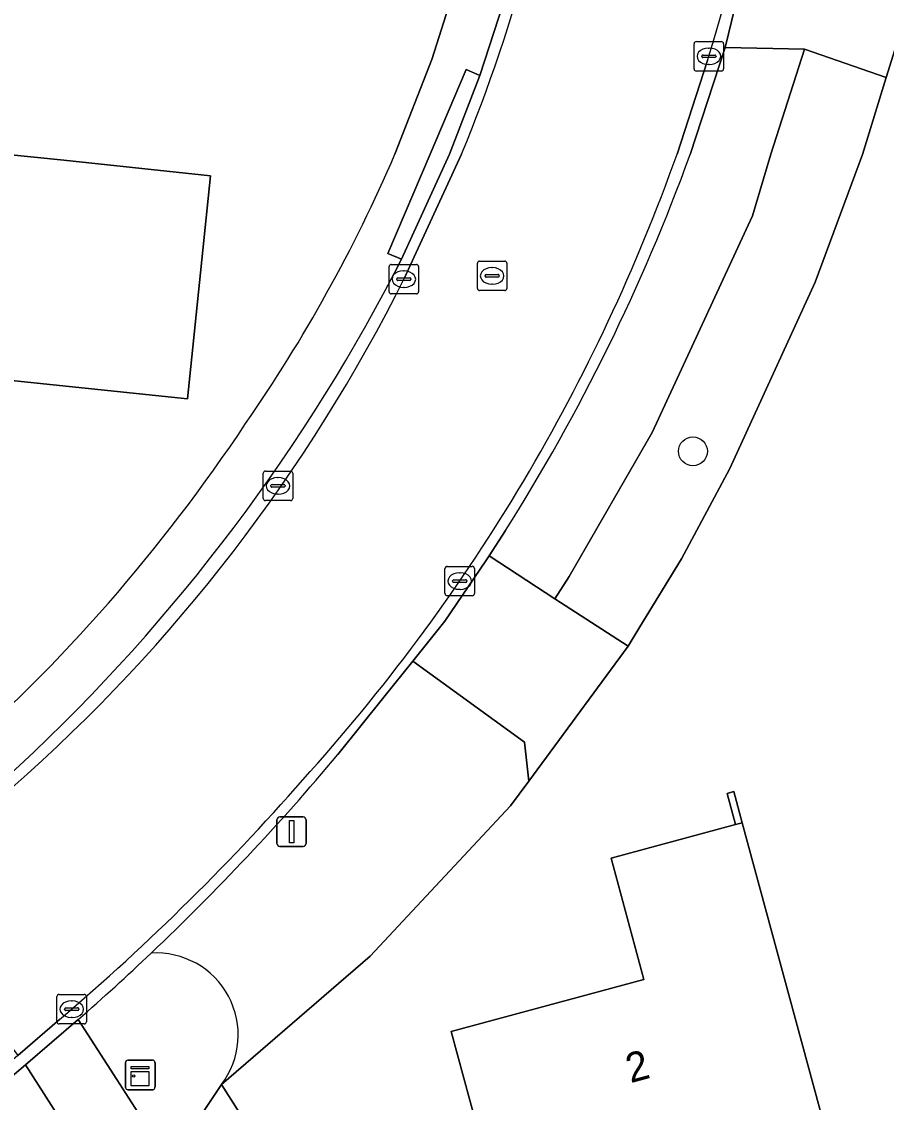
# Model space of a CAD drawing. Extents: x 162156 to 163172, y 378995 to 380779.
# Drawn here: x 162699.46 to 162728.79, y 380217.85 to 380254.49 of the extents above; entities that cross this region are included whole.
import ezdxf

# ---------------------------------------------------------------- set-up
doc = ezdxf.new("R2010")
doc.units = 0
for name, color, linetype in [('IMGEO_Berm_groen', 7, 'Continuous'), ('IMGEO_Boom', 7, 'Continuous'), ('IMGEO_Erf', 7, 'Continuous'), ('IMGEO_Gemengd_bos', 7, 'Continuous'), ('IMGEO_Groenvoorziening', 7, 'Continuous'), ('IMGEO_Kast', 7, 'Continuous'), ('IMGEO_Kolk', 7, 'Continuous'), ('IMGEO_Lichtmast', 7, 'Continuous'), ('IMGEO_Muur', 7, 'Continuous'), ('IMGEO_Naaldbos', 7, 'Continuous'), ('IMGEO_Pand', 7, 'Continuous'), ('IMGEO_Pand_nummerreeks', 7, 'Continuous'), ('IMGEO_Rijbaan_lokaal_gesloten', 7, 'Continuous'), ('IMGEO_Rijbaan_lokaal_open', 7, 'Continuous'), ('IMGEO_Rioolput', 7, 'Continuous'), ('IMGEO_Voetpad_open', 7, 'Continuous')]:
    doc.layers.add(name, color=color, linetype=linetype)

msp = doc.modelspace()

# ---------------------------------------------------------------- linework, layer by layer
at = {"layer": 'IMGEO_Berm_groen'}
for points in [[(162724.25, 380247.911), (162724.87, 380250), (162726.015, 380253.554), (162723.325, 380253.61), (162722.132, 380249.986)], [(162715.868, 380237.236), (162715.311, 380236.375), (162717.542, 380234.926), (162718.034, 380235.684), (162720.848, 380240.557), (162724.25, 380247.911)], [(162716.04, 380227.906), (162716.33, 380228.299), (162716.656, 380228.741), (162716.518, 380230.059), (162712.728, 380232.813), (162711.744, 380231.585), (162710.188, 380229.645)], [(162706.233, 380218.452), (162711.278, 380222.808), (162716.04, 380227.906)]]:
    msp.add_lwpolyline(points, dxfattribs=at)
for centre, radius, start, end in [((162659.962, 380272.616), 66.161, 327.6724, 339.99837), ((162647.786, 380282.027), 81.473, 313.481, 319.98881), ((162704.023, 380220.137), 2.779, 322.6763, 93.5967)]:
    msp.add_arc(centre, radius, start, end, dxfattribs=at)
at = {"layer": 'IMGEO_Boom'}
msp.add_circle((162722.227, 380239.922), 0.489, dxfattribs=at)
at = {"layer": 'IMGEO_Erf'}
for points in [[(162729.987, 380256.471), (162728.785, 380252.601), (162727.974, 380249.988), (162726.374, 380245.66), (162723.48, 380239.34), (162721.842, 380236.275), (162720.429, 380233.968), (162720.027, 380233.312), (162716.656, 380228.741), (162716.33, 380228.299), (162716.04, 380227.906), (162711.278, 380222.808), (162706.233, 380218.452), (162718.287, 380199.505), (162748.489, 380207.589), (162771.731, 380247.855), (162782.999, 380245.41), (162784.806, 380245.018), (162783.44, 380250), (162783.125, 380251.148), (162766.255, 380312.701)], [(162712.119, 380249.993), (162713.375, 380253.205), (162714.415, 380256.486)]]:
    msp.add_lwpolyline(points, dxfattribs=at)
for points in [[(162705.865, 380249.258), (162705.079, 380241.702), (162698.129, 380242.425), (162697.655, 380237.87), (162690.598, 380238.604), (162683.739, 380239.318), (162684.232, 380244.05), (162677.199, 380244.782), (162677.752, 380250), (162677.99, 380252.246), (162682.978, 380251.727), (162688.325, 380251.17), (162688.203, 380250), (162688.117, 380249.076), (162691.674, 380248.706), (162695.331, 380248.325), (162695.502, 380250), (162695.539, 380250.351), (162698.878, 380250), (162700.894, 380249.788)], [(162723.676, 380227.271), (162723.391, 380228.324), (162723.613, 380228.384), (162723.898, 380227.331), (162727.126, 380215.415), (162727.078, 380215.402), (162727.938, 380212.224), (162724.863, 380211.392), (162725.053, 380210.691), (162716.775, 380208.449), (162717.488, 380205.816), (162717.199, 380205.737), (162716.486, 380208.371), (162714.391, 380216.104), (162715.097, 380216.296), (162714.027, 380220.249), (162720.566, 380222.02), (162719.453, 380226.127)]]:
    msp.add_lwpolyline(points, close=True, dxfattribs=at)
for centre, radius, start, end in [((162664.268, 380270.579), 52.091, 325.2183, 336.7226), ((162659.012, 380272.768), 57.67, 311.18248, 326.4104)]:
    msp.add_arc(centre, radius, start, end, dxfattribs=at)
at = {"layer": 'IMGEO_Gemengd_bos'}
msp.add_lwpolyline([(162727.791, 380464.262), (162728.963, 380460.227), (162739.025, 380425.583), (162745.395, 380400.219), (162786.126, 380251.585), (162786.56, 380250), (162795.456, 380217.538), (162794.037, 380217.15), (162792.555, 380216.745), (162791.089, 380216.345), (162783.48, 380243.983), (162782.999, 380245.41), (162771.731, 380247.855), (162748.489, 380207.589), (162718.287, 380199.505), (162706.233, 380218.452), (162704.484, 380215.83), (162716.066, 380197.828)], dxfattribs=at)
at = {"layer": 'IMGEO_Groenvoorziening'}
msp.add_lwpolyline([(162726.374, 380245.66), (162727.974, 380249.988), (162728.785, 380252.601), (162726.015, 380253.554), (162724.87, 380250), (162724.25, 380247.911), (162720.848, 380240.557), (162718.034, 380235.684), (162717.542, 380234.926), (162720.027, 380233.312), (162720.429, 380233.968), (162721.842, 380236.275), (162723.48, 380239.34)], close=True, dxfattribs=at)
msp.add_lwpolyline([(162701.377, 380220.66), (162702.687, 380218.624), (162703.803, 380216.889), (162704.484, 380215.83), (162706.233, 380218.452)], dxfattribs=at)
for centre, radius, start, end in [((162704.023, 380220.137), 2.779, 322.6763, 93.5967), ((162649.479, 380280.162), 78.955, 311.09534, 313.52121)]:
    msp.add_arc(centre, radius, start, end, dxfattribs=at)
at = {"layer": 'IMGEO_Kast'}
for p, q in [((162703.056, 380219.281), (162703.897, 380219.281)), ((162703.897, 380219.281), (162703.056, 380219.281)), ((162702.981, 380218.356), (162702.981, 380219.197)), ((162702.981, 380219.197), (162702.981, 380218.356)), ((162703.981, 380219.206), (162703.981, 380218.365)), ((162703.981, 380218.365), (162703.981, 380219.206)), ((162703.906, 380218.281), (162703.065, 380218.281)), ((162703.065, 380218.281), (162703.906, 380218.281))]:
    msp.add_line(p, q, dxfattribs=at)
for points in [[(162703.176, 380219.071), (162703.776, 380219.071), (162703.776, 380218.986), (162703.176, 380218.986), (162703.176, 380219.071)], [(162703.176, 380218.896), (162703.776, 380218.896), (162703.776, 380218.407), (162703.176, 380218.407), (162703.176, 380218.896)]]:
    msp.add_lwpolyline(points, dxfattribs=at)
msp.add_circle((162703.26, 380218.745), 0.0377, dxfattribs=at)
for centre, start, end in [((162703.059, 380219.203), 92.4484, 184.2845), ((162703.059, 380219.203), 92.4484, 184.2845), ((162703.903, 380219.203), 2.4484, 94.2845), ((162703.903, 380219.203), 2.4484, 94.2845), ((162703.059, 380218.359), 182.4484, 274.2845), ((162703.059, 380218.359), 182.4484, 274.2845), ((162703.903, 380218.359), 272.4484, 4.2845), ((162703.903, 380218.359), 272.4484, 4.2845)]:
    msp.add_arc(centre, 0.0779, start, end, dxfattribs=at)
at = {"layer": 'IMGEO_Kolk'}
for p, q in [((162722.267, 380252.888), (162722.267, 380253.74)), ((162722.342, 380253.814), (162723.194, 380253.814)), ((162723.268, 380253.74), (162723.268, 380252.888)), ((162722.569, 380253.357), (162722.967, 380253.357)), ((162722.755, 380253.594), (162722.78, 380253.594)), ((162722.526, 380253.308), (162722.526, 380253.32)), ((162722.964, 380253.271), (162722.566, 380253.271)), ((162722.778, 380253.034), (162722.753, 380253.034)), ((162723.01, 380253.32), (162723.01, 380253.308)), ((162723.194, 380252.814), (162722.342, 380252.814)), ((162711.921, 380245.333), (162711.921, 380246.185)), ((162711.996, 380246.259), (162712.848, 380246.259)), ((162712.409, 380246.039), (162712.434, 380246.039)), ((162712.922, 380246.185), (162712.922, 380245.333)), ((162712.18, 380245.753), (162712.18, 380245.765)), ((162712.618, 380245.716), (162712.22, 380245.716)), ((162712.223, 380245.802), (162712.621, 380245.802)), ((162712.664, 380245.765), (162712.664, 380245.753)), ((162712.432, 380245.479), (162712.407, 380245.479)), ((162712.848, 380245.259), (162711.996, 380245.259)), ((162707.65, 380238.326), (162707.65, 380239.178)), ((162707.725, 380239.252), (162708.577, 380239.252)), ((162708.651, 380239.178), (162708.651, 380238.326)), ((162707.909, 380238.746), (162707.909, 380238.758)), ((162708.347, 380238.709), (162707.949, 380238.709)), ((162707.952, 380238.795), (162708.35, 380238.795)), ((162708.138, 380239.032), (162708.163, 380239.032)), ((162708.393, 380238.758), (162708.393, 380238.746)), ((162708.161, 380238.472), (162708.136, 380238.472)), ((162708.577, 380238.252), (162707.725, 380238.252)), ((162713.817, 380235.097), (162713.817, 380235.949)), ((162713.892, 380236.023), (162714.744, 380236.023)), ((162714.305, 380235.803), (162714.33, 380235.803)), ((162714.818, 380235.949), (162714.818, 380235.097)), ((162714.076, 380235.517), (162714.076, 380235.529)), ((162714.514, 380235.48), (162714.116, 380235.48)), ((162714.119, 380235.566), (162714.517, 380235.566)), ((162714.56, 380235.529), (162714.56, 380235.517)), ((162714.744, 380235.023), (162713.892, 380235.023)), ((162714.328, 380235.243), (162714.303, 380235.243)), ((162700.731, 380221.509), (162701.583, 380221.509)), ((162700.656, 380220.583), (162700.656, 380221.435)), ((162701.144, 380221.289), (162701.169, 380221.289)), ((162701.657, 380221.435), (162701.657, 380220.583)), ((162700.915, 380221.003), (162700.915, 380221.015)), ((162701.353, 380220.966), (162700.955, 380220.966)), ((162700.958, 380221.052), (162701.356, 380221.052)), ((162701.167, 380220.729), (162701.142, 380220.729)), ((162701.399, 380221.015), (162701.399, 380221.003)), ((162701.583, 380220.509), (162700.731, 380220.509))]:
    msp.add_line(p, q, dxfattribs=at)
for points in [[(162722.267, 380252.888), (162722.267, 380253.74)], [(162722.342, 380253.814), (162723.194, 380253.814)], [(162723.268, 380253.74), (162723.268, 380252.888)], [(162723.194, 380252.814), (162722.342, 380252.814)], [(162711.921, 380245.333), (162711.921, 380246.185)], [(162711.996, 380246.259), (162712.848, 380246.259)], [(162712.922, 380246.185), (162712.922, 380245.333)], [(162712.848, 380245.259), (162711.996, 380245.259)], [(162707.65, 380238.326), (162707.65, 380239.178)], [(162707.725, 380239.252), (162708.577, 380239.252)], [(162708.651, 380239.178), (162708.651, 380238.326)], [(162708.577, 380238.252), (162707.725, 380238.252)], [(162713.817, 380235.097), (162713.817, 380235.949)], [(162713.892, 380236.023), (162714.744, 380236.023)], [(162714.818, 380235.949), (162714.818, 380235.097)], [(162714.744, 380235.023), (162713.892, 380235.023)], [(162700.731, 380221.509), (162701.583, 380221.509)], [(162700.656, 380220.583), (162700.656, 380221.435)], [(162701.657, 380221.435), (162701.657, 380220.583)], [(162701.583, 380220.509), (162700.731, 380220.509)]]:
    msp.add_lwpolyline(points, dxfattribs=at)
for centre, radius, start, end in [((162722.344, 380253.738), 0.0765, 91.552, 178.448), ((162722.344, 380253.738), 0.0765, 91.552, 178.448), ((162723.192, 380253.738), 0.0765, 1.552, 88.448), ((162723.192, 380253.738), 0.0765, 1.552, 88.448), ((162722.566, 380253.317), 0.0403, 85.8775, 175.7526), ((162722.971, 380253.319), 0.0386, 1.7309, 96.639), ((162722.563, 380253.307), 0.0366, 178.938, 274.7102), ((162722.967, 380253.314), 0.043, 264.8664, 352.4533), ((162722.344, 380252.89), 0.0765, 181.552, 268.448), ((162722.344, 380252.89), 0.0765, 181.552, 268.448), ((162723.192, 380252.89), 0.0765, 271.552, 358.448), ((162723.192, 380252.89), 0.0765, 271.552, 358.448), ((162711.998, 380246.183), 0.0765, 91.552, 178.448), ((162711.998, 380246.183), 0.0765, 91.552, 178.448), ((162712.846, 380246.183), 0.0765, 1.552, 88.448), ((162712.846, 380246.183), 0.0765, 1.552, 88.448), ((162712.22, 380245.762), 0.0403, 85.8775, 175.7526), ((162712.217, 380245.752), 0.0366, 178.938, 274.7102), ((162712.621, 380245.759), 0.043, 264.8664, 352.4533), ((162712.625, 380245.764), 0.0386, 1.7309, 96.639), ((162711.998, 380245.335), 0.0765, 181.552, 268.448), ((162711.998, 380245.335), 0.0765, 181.552, 268.448), ((162712.846, 380245.335), 0.0765, 271.552, 358.448), ((162712.846, 380245.335), 0.0765, 271.552, 358.448), ((162707.727, 380239.176), 0.0765, 91.552, 178.448), ((162707.727, 380239.176), 0.0765, 91.552, 178.448), ((162708.575, 380239.176), 0.0765, 1.552, 88.448), ((162708.575, 380239.176), 0.0765, 1.552, 88.448), ((162707.949, 380238.755), 0.0403, 85.8775, 175.7526), ((162707.946, 380238.745), 0.0366, 178.938, 274.7102), ((162708.35, 380238.752), 0.043, 264.8664, 352.4533), ((162708.354, 380238.757), 0.0386, 1.7309, 96.639), ((162707.727, 380238.328), 0.0765, 181.552, 268.448), ((162707.727, 380238.328), 0.0765, 181.552, 268.448), ((162708.575, 380238.328), 0.0765, 271.552, 358.448), ((162708.575, 380238.328), 0.0765, 271.552, 358.448), ((162713.894, 380235.947), 0.0765, 91.552, 178.448), ((162713.894, 380235.947), 0.0765, 91.552, 178.448), ((162714.742, 380235.947), 0.0765, 1.552, 88.448), ((162714.742, 380235.947), 0.0765, 1.552, 88.448), ((162714.116, 380235.526), 0.0403, 85.8775, 175.7526), ((162714.113, 380235.516), 0.0366, 178.938, 274.7102), ((162714.517, 380235.523), 0.043, 264.8664, 352.4533), ((162714.521, 380235.528), 0.0386, 1.7309, 96.639), ((162713.894, 380235.099), 0.0765, 181.552, 268.448), ((162713.894, 380235.099), 0.0765, 181.552, 268.448), ((162714.742, 380235.099), 0.0765, 271.552, 358.448), ((162714.742, 380235.099), 0.0765, 271.552, 358.448), ((162700.733, 380221.433), 0.0765, 91.552, 178.448), ((162700.733, 380221.433), 0.0765, 91.552, 178.448), ((162701.581, 380221.433), 0.0765, 1.552, 88.448), ((162701.581, 380221.433), 0.0765, 1.552, 88.448), ((162700.955, 380221.012), 0.0403, 85.8775, 175.7526), ((162700.952, 380221.002), 0.0366, 178.938, 274.7102), ((162701.356, 380221.009), 0.043, 264.8664, 352.4533), ((162701.36, 380221.014), 0.0386, 1.7309, 96.639), ((162700.733, 380220.585), 0.0765, 181.552, 268.448), ((162700.733, 380220.585), 0.0765, 181.552, 268.448), ((162701.581, 380220.585), 0.0765, 271.552, 358.448), ((162701.581, 380220.585), 0.0765, 271.552, 358.448)]:
    msp.add_arc(centre, radius, start, end, dxfattribs=at)
for centre, major_axis, ratio, start_param, end_param in [((162722.754, 380253.314), (-0.387, 0.002), 0.722429, 4.712389, 7.853982), ((162722.779, 380253.314), (-0.39, 0.002), 0.717154, 1.570796, 4.712389), ((162712.408, 380245.759), (-0.387, 0.002), 0.722429, 4.712389, 7.853982), ((162712.433, 380245.759), (-0.39, 0.002), 0.717154, 1.570796, 4.712389), ((162708.137, 380238.752), (-0.387, 0.002), 0.722429, 4.712389, 7.853982), ((162708.162, 380238.752), (-0.39, 0.002), 0.717154, 1.570796, 4.712389), ((162714.304, 380235.523), (-0.387, 0.002), 0.722429, 4.712389, 7.853982), ((162714.329, 380235.523), (-0.39, 0.002), 0.717154, 1.570796, 4.712389), ((162701.143, 380221.009), (-0.387, 0.002), 0.722429, 4.712389, 7.853982), ((162701.168, 380221.009), (-0.39, 0.002), 0.717154, 1.570796, 4.712389)]:
    msp.add_ellipse(centre, major_axis=major_axis, ratio=ratio, start_param=start_param, end_param=end_param, dxfattribs=at)
at = {"layer": 'IMGEO_Lichtmast'}
for p, q in [((162708.119, 380226.629), (162708.119, 380227.429)), ((162708.119, 380227.429), (162708.119, 380226.629)), ((162708.219, 380227.529), (162709.009, 380227.529)), ((162709.009, 380227.529), (162708.219, 380227.529)), ((162709.109, 380227.429), (162709.109, 380226.629)), ((162709.109, 380226.629), (162709.109, 380227.429)), ((162709.009, 380226.529), (162708.219, 380226.529)), ((162708.219, 380226.529), (162709.009, 380226.529))]:
    msp.add_line(p, q, dxfattribs=at)
msp.add_lwpolyline([(162708.539, 380227.404), (162708.689, 380227.404), (162708.689, 380226.654), (162708.539, 380226.654), (162708.539, 380227.404)], dxfattribs=at)
for centre, start, end in [((162708.219, 380227.429), 90, 180), ((162708.219, 380227.429), 90, 180), ((162709.009, 380227.429), 0, 90), ((162709.009, 380227.429), 360, 90), ((162708.219, 380226.629), 180, 270), ((162708.219, 380226.629), 180, 270), ((162709.009, 380226.629), 270, 0), ((162709.009, 380226.629), 270, 0)]:
    msp.add_arc(centre, 0.1, start, end, dxfattribs=at)
at = {"layer": 'IMGEO_Muur'}
msp.add_lwpolyline([(162723.898, 380227.331), (162723.613, 380228.384), (162723.391, 380228.324), (162723.676, 380227.271)], close=True, dxfattribs=at)
at = {"layer": 'IMGEO_Naaldbos'}
msp.add_lwpolyline([(162714.53, 380195.758), (162699.587, 380219.124), (162691.747, 380212.48), (162698.703, 380201.605)], dxfattribs=at)
at = {"layer": 'IMGEO_Pand'}
for points in [[(162691.674, 380248.706), (162690.598, 380238.604), (162697.655, 380237.87), (162698.129, 380242.425), (162705.079, 380241.702), (162705.865, 380249.258), (162700.894, 380249.788), (162698.878, 380250), (162695.539, 380250.351), (162695.502, 380250), (162695.331, 380248.325)], [(162723.898, 380227.331), (162723.676, 380227.271), (162719.453, 380226.127), (162720.566, 380222.02), (162714.027, 380220.249), (162715.097, 380216.296), (162714.391, 380216.104), (162716.486, 380208.371), (162716.775, 380208.449), (162725.053, 380210.691), (162724.863, 380211.392), (162727.938, 380212.224), (162727.078, 380215.402), (162727.126, 380215.415)]]:
    msp.add_lwpolyline(points, close=True, dxfattribs=at)
at = {"layer": 'IMGEO_Rijbaan_lokaal_gesloten'}
for points in [[(162717.077, 380260.063), (162715.949, 380255.588), (162714.997, 380252.669), (162713.968, 380250), (162712.341, 380246.437), (162712.108, 380245.976)], [(162721.688, 380250), (162722.721, 380253.167)], [(162714.381, 380250), (162712.446, 380245.803)], [(162712.446, 380245.803), (162714.381, 380250)], [(162699.134, 380228.52), (162695.142, 380225.055), (162699.326, 380219.441), (162700.746, 380220.657)]]:
    msp.add_lwpolyline(points, dxfattribs=at)
for centre, radius, start, end in [((162662.053, 380271.539), 56.587, 337.6267, 7.1636), ((162662.053, 380271.539), 56.587, 337.6267, 7.1636), ((162664.62, 380271.236), 60.846, 342.72441, 4.80589), ((162662.28, 380271.145), 63.059, 318.13754, 340.40777), ((162657.086, 380274.678), 62.058, 312.33652, 332.45184), ((162661.623, 380271.181), 56.807, 311.3249, 333.4656), ((162661.623, 380271.181), 56.807, 311.3249, 333.4656), ((162648.599, 380281.866), 80.41, 310.4293, 318.95378)]:
    msp.add_arc(centre, radius, start, end, dxfattribs=at)
at = {"layer": 'IMGEO_Rijbaan_lokaal_open'}
for points in [[(162722.132, 380249.986), (162723.325, 380253.61), (162724.29, 380257.618)], [(162722.721, 380253.167), (162721.688, 380250)], [(162710.188, 380229.645), (162711.744, 380231.585), (162712.728, 380232.813), (162713.808, 380234.16), (162715.202, 380236.206), (162715.311, 380236.375), (162715.868, 380237.236)], [(162655.18, 380181.877), (162688.009, 380209.266), (162691.747, 380212.48), (162699.587, 380219.124), (162701.377, 380220.66)], [(162700.746, 380220.657), (162699.326, 380219.441), (162688.108, 380209.839), (162656.75, 380183.582)]]:
    msp.add_lwpolyline(points, dxfattribs=at)
for centre, radius, start, end in [((162664.62, 380271.236), 60.846, 342.72441, 4.80589), ((162662.28, 380271.145), 63.059, 318.13754, 340.40777), ((162659.962, 380272.616), 66.161, 327.6724, 339.99837), ((162647.786, 380282.027), 81.473, 313.481, 319.98881), ((162648.599, 380281.866), 80.41, 310.4293, 318.95378), ((162649.479, 380280.162), 78.955, 311.09534, 313.52121)]:
    msp.add_arc(centre, radius, start, end, dxfattribs=at)
at = {"layer": 'IMGEO_Rioolput'}
for p, q in [((162714.99, 380246.37), (162715.842, 380246.37)), ((162714.915, 380245.444), (162714.915, 380246.296)), ((162715.403, 380246.15), (162715.428, 380246.15)), ((162715.916, 380246.296), (162715.916, 380245.444)), ((162715.174, 380245.864), (162715.174, 380245.876)), ((162715.612, 380245.827), (162715.214, 380245.827)), ((162715.217, 380245.913), (162715.615, 380245.913)), ((162715.658, 380245.876), (162715.658, 380245.864)), ((162715.842, 380245.37), (162714.99, 380245.37)), ((162715.426, 380245.59), (162715.401, 380245.59))]:
    msp.add_line(p, q, dxfattribs=at)
for points in [[(162714.99, 380246.37), (162715.842, 380246.37)], [(162714.915, 380245.444), (162714.915, 380246.296)], [(162715.916, 380246.296), (162715.916, 380245.444)], [(162715.842, 380245.37), (162714.99, 380245.37)]]:
    msp.add_lwpolyline(points, dxfattribs=at)
for centre, radius, start, end in [((162714.992, 380246.294), 0.0765, 91.552, 178.448), ((162714.992, 380246.294), 0.0765, 91.552, 178.448), ((162715.84, 380246.294), 0.0765, 1.552, 88.448), ((162715.84, 380246.294), 0.0765, 1.552, 88.448), ((162715.214, 380245.873), 0.0403, 85.8775, 175.7526), ((162715.211, 380245.863), 0.0366, 178.938, 274.7102), ((162715.615, 380245.87), 0.043, 264.8664, 352.4533), ((162715.619, 380245.875), 0.0386, 1.7309, 96.639), ((162714.992, 380245.446), 0.0765, 181.552, 268.448), ((162714.992, 380245.446), 0.0765, 181.552, 268.448), ((162715.84, 380245.446), 0.0765, 271.552, 358.448), ((162715.84, 380245.446), 0.0765, 271.552, 358.448)]:
    msp.add_arc(centre, radius, start, end, dxfattribs=at)
for centre, major_axis, ratio, start_param, end_param in [((162715.402, 380245.87), (-0.387, 0.002), 0.722429, 4.712389, 7.853982), ((162715.427, 380245.87), (-0.39, 0.002), 0.717154, 1.570796, 4.712389)]:
    msp.add_ellipse(centre, major_axis=major_axis, ratio=ratio, start_param=start_param, end_param=end_param, dxfattribs=at)
at = {"layer": 'IMGEO_Voetpad_open'}
for points in [[(162712.108, 380245.976), (162712.341, 380246.437), (162711.882, 380246.633), (162713.317, 380250), (162714.538, 380252.865), (162714.997, 380252.669), (162715.949, 380255.588), (162715.465, 380255.709), (162716.592, 380260.184), (162717.077, 380260.063)], [(162714.415, 380256.486), (162713.375, 380253.205), (162712.119, 380249.993)], [(162716.066, 380197.828), (162704.484, 380215.83), (162703.803, 380216.889), (162702.687, 380218.624), (162701.377, 380220.66), (162699.587, 380219.124), (162714.53, 380195.758)]]:
    msp.add_lwpolyline(points, dxfattribs=at)
for points in [[(162726.015, 380253.554), (162728.785, 380252.601), (162729.987, 380256.471), (162727.064, 380257.059), (162724.29, 380257.618), (162723.325, 380253.61)], [(162714.997, 380252.669), (162714.538, 380252.865), (162713.317, 380250), (162711.882, 380246.633), (162712.341, 380246.437), (162713.968, 380250)], [(162720.027, 380233.312), (162717.542, 380234.926), (162715.311, 380236.375), (162715.202, 380236.206), (162713.808, 380234.16), (162712.728, 380232.813), (162716.518, 380230.059), (162716.656, 380228.741)]]:
    msp.add_lwpolyline(points, close=True, dxfattribs=at)
for centre, radius, start, end in [((162664.268, 380270.579), 52.091, 325.2183, 336.7226), ((162657.086, 380274.678), 62.058, 312.33652, 332.45184), ((162659.012, 380272.768), 57.67, 311.18248, 326.4104)]:
    msp.add_arc(centre, radius, start, end, dxfattribs=at)

# ---------------------------------------------------------------- texts
at = {"layer": 'IMGEO_Pand_nummerreeks'}
msp.add_text('2', height=1, rotation=15.1547, dxfattribs=at).set_placement((162720.109, 380218.498))

doc.saveas('drawing.dxf')
